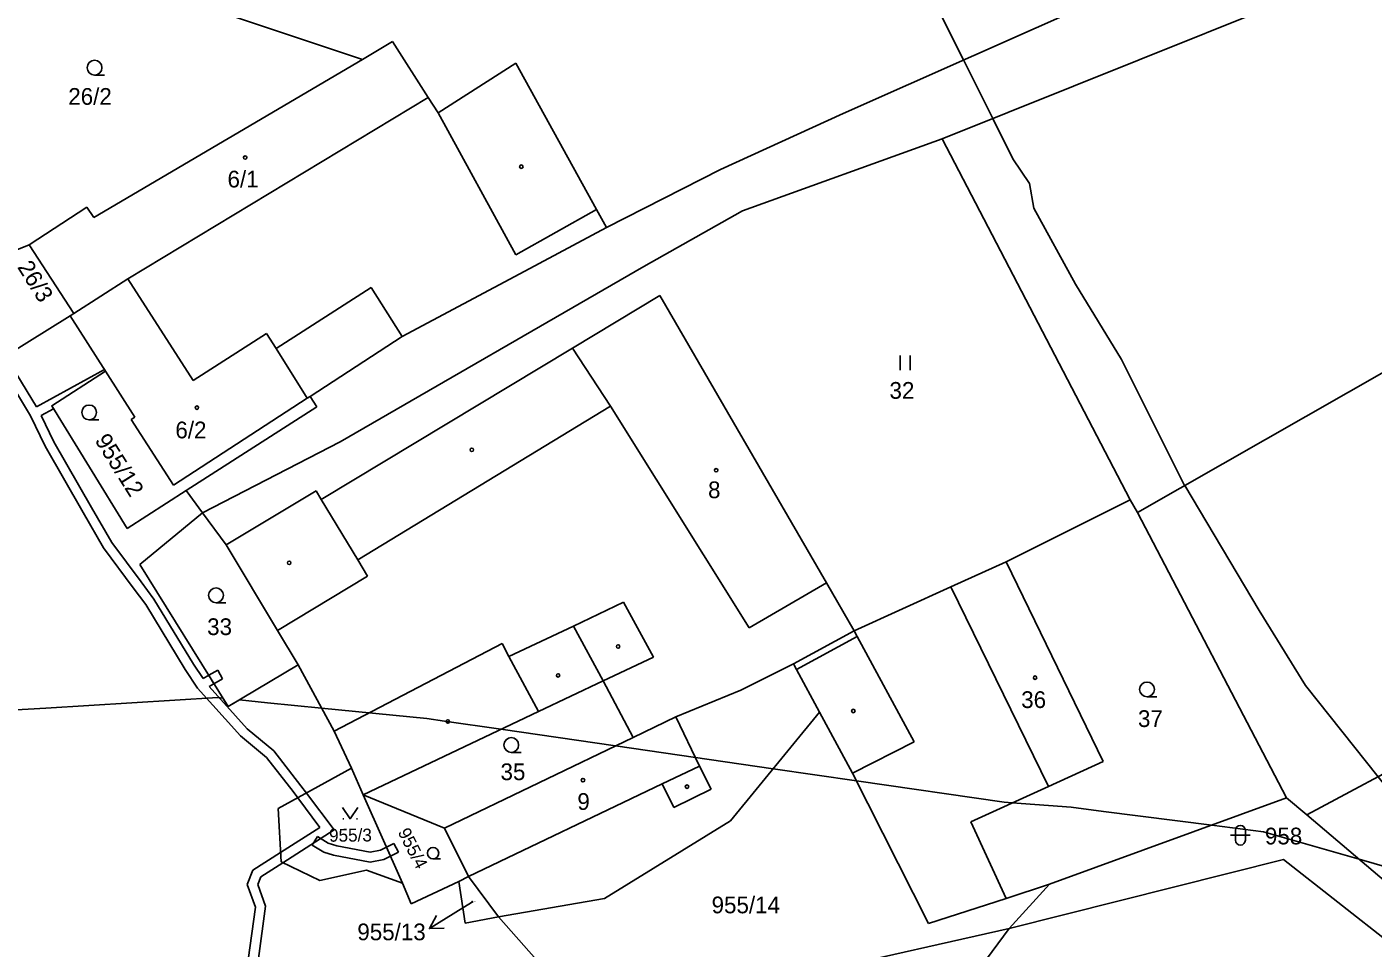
# Model space of a CAD drawing. Extents: x -749173 to -746119, y -1132678 to -1130338.
# Drawn here: x -747827.1 to -747690.2, y -1130989.1 to -1130895.5 of the extents above; entities that cross this region are included whole.
import ezdxf

# ---------------------------------------------------------------- set-up
doc = ezdxf.new("R2010")
doc.units = 0
for name, color, linetype in [('Vrstva 1', 7, 'Continuous'), ('Vrstva 16', 7, 'Continuous'), ('Vrstva 18', 7, 'Continuous'), ('Vrstva 19', 7, 'Continuous'), ('Vrstva 25', 7, 'Continuous'), ('Vrstva 3', 7, 'Continuous'), ('Vrstva 30', 7, 'Continuous'), ('Vrstva 37', 7, 'Continuous'), ('Vrstva 4', 7, 'Continuous'), ('Vrstva 52', 7, 'Continuous'), ('Vrstva 6', 7, 'Continuous')]:
    doc.layers.add(name, color=color, linetype=linetype)

msp = doc.modelspace()

# ---------------------------------------------------------------- linework, layer by layer
at = {"layer": 'Vrstva 1'}
for p, q in [((-747831.83, -1130919.6), (-747826.88, -1130917.6)), ((-747822.73, -1130924.82), (-747829.18, -1130928.84))]:
    msp.add_line(p, q, dxfattribs=at)
for points in [[(-747680.49, -1130885.34), (-747734.07, -1130906.85)], [(-747825.73, -1130887.83), (-747793.01, -1130898.76)], [(-747744.11, -1130904.25), (-747711.23, -1130889.62)], [(-747793.01, -1130898.76), (-747789.93, -1130896.95)], [(-747789.93, -1130896.95), (-747786.33, -1130902.63)], [(-747793.01, -1130898.76), (-747820.31, -1130914.83)], [(-747785.31, -1130904.19), (-747777.39, -1130899.14)], [(-747777.39, -1130899.14), (-747769.2, -1130914.03)], [(-747786.33, -1130902.63), (-747785.31, -1130904.19)], [(-747756.58, -1130909.94), (-747744.11, -1130904.25)], [(-747754.36, -1130914.15), (-747734.07, -1130906.85)], [(-747734.07, -1130906.85), (-747714.93, -1130943.52)], [(-747768.2, -1130915.84), (-747756.58, -1130909.94)], [(-747826.88, -1130917.6), (-747821.04, -1130913.77)], [(-747821.04, -1130913.77), (-747820.31, -1130914.83)], [(-747769.2, -1130914.03), (-747768.2, -1130915.84)], [(-747764.38, -1130919.82), (-747754.36, -1130914.15)], [(-747776.49, -1130920.27), (-747768.2, -1130915.84)], [(-747822.35, -1130924.58), (-747826.88, -1130917.6)], [(-747795.26, -1130937.61), (-747764.38, -1130919.82)], [(-747816.84, -1130921.05), (-747822.35, -1130924.58)], [(-747810.2, -1130931.39), (-747816.84, -1130921.05)], [(-747788.95, -1130926.93), (-747776.49, -1130920.27)], [(-747801.79, -1130928.13), (-747792.11, -1130921.93)], [(-747788.95, -1130926.93), (-747792.11, -1130921.93)], [(-747762.77, -1130922.74), (-747771.66, -1130928.1)], [(-747745.82, -1130951.95), (-747762.77, -1130922.74)], [(-747822.73, -1130924.82), (-747822.35, -1130924.58)], [(-747819.12, -1130930.45), (-747822.73, -1130924.82)], [(-747802.76, -1130926.61), (-747810.2, -1130931.39)], [(-747802.76, -1130926.61), (-747801.79, -1130928.13)], [(-747798.33, -1130933.02), (-747788.95, -1130926.93)], [(-747771.66, -1130928.1), (-747797.2, -1130943.47)], [(-747819.12, -1130930.45), (-747824.59, -1130933.96)], [(-747816.13, -1130935.12), (-747819.12, -1130930.45)], [(-747812.22, -1130942.04), (-747798.61, -1130933.2)], [(-747798.61, -1130933.2), (-747798.33, -1130933.02)], [(-747798.33, -1130933.02), (-747797.65, -1130934.06)], [(-747816.91, -1130946.43), (-747824.59, -1130933.96)], [(-747797.65, -1130934.06), (-747810.92, -1130942.58)], [(-747816.51, -1130935.36), (-747816.13, -1130935.12)], [(-747812.22, -1130942.04), (-747816.51, -1130935.36)], [(-747809.25, -1130944.84), (-747795.26, -1130937.61)], [(-747810.92, -1130942.58), (-747816.91, -1130946.43)], [(-747809.25, -1130944.84), (-747810.92, -1130942.58)], [(-747806.85, -1130948.1), (-747797.72, -1130942.61)], [(-747797.72, -1130942.61), (-747797.2, -1130943.47)], [(-747714.93, -1130943.52), (-747727.56, -1130949.81)], [(-747714.93, -1130943.52), (-747714.21, -1130944.8)], [(-747815.62, -1130950.1), (-747809.25, -1130944.84)], [(-747806.85, -1130948.1), (-747809.25, -1130944.84)], [(-747714.21, -1130944.8), (-747699.04, -1130973.8)], [(-747801.65, -1130956.79), (-747806.85, -1130948.1)], [(-747727.56, -1130949.81), (-747733.16, -1130952.36)], [(-747727.56, -1130949.81), (-747717.69, -1130970.09)], [(-747806.65, -1130964.52), (-747815.62, -1130950.1)], [(-747745.82, -1130951.95), (-747743.01, -1130956.84)], [(-747733.16, -1130952.36), (-747743.01, -1130956.84)], [(-747801.65, -1130956.79), (-747799.54, -1130960.27)], [(-747749.19, -1130960.19), (-747743.01, -1130956.84)], [(-747799.54, -1130960.27), (-747806.65, -1130964.52)], [(-747795.87, -1130967.04), (-747799.54, -1130960.27)], [(-747754.52, -1130962.87), (-747749.19, -1130960.19)], [(-747749.19, -1130960.19), (-747748.88, -1130960.76)], [(-747748.88, -1130960.76), (-747746.53, -1130965.11)], [(-747775.11, -1130965.02), (-747768.52, -1130961.91)], [(-747768.52, -1130961.91), (-747765.48, -1130967.66)], [(-747761.14, -1130965.57), (-747754.52, -1130962.87)], [(-747775.11, -1130965.02), (-747792.94, -1130973.48)], [(-747761.14, -1130965.57), (-747765.48, -1130967.66)], [(-747755.59, -1130976.12), (-747746.53, -1130965.11)], [(-747746.53, -1130965.11), (-747743.17, -1130971.3)], [(-747794.11, -1130970.77), (-747795.87, -1130967.04)], [(-747765.48, -1130967.66), (-747784.66, -1130976.88)], [(-747717.69, -1130970.09), (-747723.26, -1130972.63)], [(-747794.11, -1130970.77), (-747801.56, -1130974.89)], [(-747792.94, -1130973.48), (-747794.11, -1130970.77)], [(-747735.45, -1130986.58), (-747743.17, -1130971.3)], [(-747723.26, -1130972.63), (-747731.13, -1130976.23)], [(-747792.94, -1130973.48), (-747784.66, -1130976.88)], [(-747788.92, -1130982.46), (-747792.94, -1130973.48)], [(-747723.14, -1130982.58), (-747699.04, -1130973.8)], [(-747699.04, -1130973.8), (-747696.99, -1130975.53)], [(-747801.56, -1130974.89), (-747801.28, -1130980.31)], [(-747696.99, -1130975.53), (-747670.43, -1130998.05)], [(-747784.66, -1130976.88), (-747782.22, -1130981.78)], [(-747768.38, -1130984.02), (-747755.59, -1130976.12)], [(-747731.13, -1130976.23), (-747727.55, -1130984.01)], [(-747699.35, -1130980.06), (-747727.26, -1130987.09)], [(-747677.24, -1130997.39), (-747699.35, -1130980.06)], [(-747801.28, -1130980.31), (-747797.32, -1130982.19)], [(-747797.32, -1130982.19), (-747792.6, -1130981.16)], [(-747792.6, -1130981.16), (-747788.92, -1130982.46)], [(-747788.06, -1130984.58), (-747788.92, -1130982.46)], [(-747783.2, -1130982.29), (-747788.06, -1130984.58)], [(-747783.2, -1130982.29), (-747782.22, -1130981.78)], [(-747782.56, -1130986.54), (-747783.2, -1130982.29)], [(-747779.16, -1130985.88), (-747782.22, -1130981.78)], [(-747723.14, -1130982.58), (-747727.55, -1130984.01)], [(-747727.26, -1130987.09), (-747723.14, -1130982.58)], [(-747779.16, -1130985.88), (-747768.38, -1130984.02)], [(-747727.55, -1130984.01), (-747735.45, -1130986.58)], [(-747779.16, -1130985.88), (-747782.56, -1130986.54)], [(-747774.01, -1130991.73), (-747779.16, -1130985.88)], [(-747746.19, -1130991.34), (-747727.26, -1130987.09)], [(-747727.26, -1130987.09), (-747735.98, -1130998.89)]]:
    msp.add_lwpolyline(points, dxfattribs=at)
at = {"layer": 'Vrstva 16'}
msp.add_line((-747784.69, -1130987.05), (-747786.19, -1130987.09), dxfattribs=at)
for points in [[(-747782.79, -1130984.99), (-747786.19, -1130987.09), (-747785.48, -1130985.77)], [(-747781.73, -1130984.34), (-747782.79, -1130984.99)]]:
    msp.add_lwpolyline(points, dxfattribs=at)
at = {"layer": 'Vrstva 25'}
for p, q in [((-747820.24, -1130900.36), (-747819.24, -1130900.36)), ((-747738.32, -1130928.86), (-747738.32, -1130930.36)), ((-747737.32, -1130930.36), (-747737.32, -1130928.86)), ((-747820.79, -1130935.39), (-747819.79, -1130935.39)), ((-747807.89, -1130953.97), (-747806.89, -1130953.97)), ((-747713.23, -1130963.53), (-747712.23, -1130963.53)), ((-747777.87, -1130969.18), (-747776.87, -1130969.18)), ((-747794.98, -1130975.92), (-747794.9, -1130975.92)), ((-747793.6, -1130975.92), (-747793.52, -1130975.92)), ((-747704.23, -1130977.1), (-747704.23, -1130978.1)), ((-747703.23, -1130977.1), (-747703.23, -1130978.1)), ((-747704.73, -1130977.6), (-747702.73, -1130977.6)), ((-747785.82, -1130980), (-747785.05, -1130980))]:
    msp.add_line(p, q, dxfattribs=at)
msp.add_lwpolyline([(-747795.02, -1130974.77), (-747794.25, -1130975.92), (-747793.48, -1130974.77)], dxfattribs=at)
for centre, radius in [((-747820.24, -1130899.61), 0.75), ((-747804.92, -1130908.74), 0.175), ((-747776.85, -1130909.67), 0.175), ((-747820.79, -1130934.64), 0.75), ((-747809.83, -1130934.15), 0.175), ((-747781.88, -1130938.44), 0.175), ((-747757.04, -1130940.51), 0.175), ((-747800.45, -1130949.92), 0.175), ((-747807.89, -1130953.22), 0.75), ((-747767.01, -1130958.42), 0.175), ((-747773.11, -1130961.36), 0.175), ((-747724.61, -1130961.59), 0.175), ((-747713.23, -1130962.78), 0.75), ((-747743.09, -1130964.97), 0.175), ((-747784.33, -1130966.04), 0.175), ((-747777.87, -1130968.43), 0.75), ((-747770.58, -1130972), 0.175), ((-747760, -1130972.66), 0.175), ((-747785.82, -1130979.42), 0.577)]:
    msp.add_circle(centre, radius, dxfattribs=at)
for centre, start, end in [((-747703.73, -1130977.1), 0, 180), ((-747703.73, -1130978.1), 180, 0)]:
    msp.add_arc(centre, 0.5, start, end, dxfattribs=at)
at = {"layer": 'Vrstva 3'}
for points in [[(-747793.01, -1130898.76), (-747789.93, -1130896.95)], [(-747789.93, -1130896.95), (-747786.33, -1130902.63)], [(-747793.01, -1130898.76), (-747820.31, -1130914.83)], [(-747786.33, -1130902.63), (-747816.84, -1130921.05)], [(-747826.88, -1130917.6), (-747821.04, -1130913.77)], [(-747821.04, -1130913.77), (-747820.31, -1130914.83)], [(-747822.35, -1130924.58), (-747826.88, -1130917.6)], [(-747816.84, -1130921.05), (-747822.35, -1130924.58)], [(-747816.84, -1130921.05), (-747822.35, -1130924.58)], [(-747810.2, -1130931.39), (-747816.84, -1130921.05)], [(-747762.77, -1130922.74), (-747771.66, -1130928.1)], [(-747745.82, -1130951.95), (-747762.77, -1130922.74)], [(-747822.73, -1130924.82), (-747822.35, -1130924.58)], [(-747819.12, -1130930.45), (-747822.73, -1130924.82)], [(-747802.76, -1130926.61), (-747810.2, -1130931.39)], [(-747802.76, -1130926.61), (-747801.79, -1130928.13)], [(-747801.79, -1130928.13), (-747798.61, -1130933.2)], [(-747767.79, -1130934.01), (-747771.66, -1130928.1)], [(-747816.13, -1130935.12), (-747819.12, -1130930.45)], [(-747812.22, -1130942.04), (-747798.61, -1130933.2)], [(-747753.68, -1130956.54), (-747767.79, -1130934.01)], [(-747816.51, -1130935.36), (-747816.13, -1130935.12)], [(-747812.22, -1130942.04), (-747816.51, -1130935.36)], [(-747727.56, -1130949.81), (-747733.16, -1130952.36)], [(-747727.56, -1130949.81), (-747717.69, -1130970.09)], [(-747753.68, -1130956.54), (-747745.82, -1130951.95)], [(-747733.16, -1130952.36), (-747723.26, -1130972.63)], [(-747761.14, -1130965.57), (-747765.48, -1130967.66)], [(-747761.14, -1130965.57), (-747758.74, -1130970.57)], [(-747765.48, -1130967.66), (-747784.66, -1130976.88)], [(-747717.69, -1130970.09), (-747723.26, -1130972.63)], [(-747758.74, -1130970.57), (-747762.53, -1130972.38)], [(-747762.53, -1130972.38), (-747782.22, -1130981.78)], [(-747784.66, -1130976.88), (-747782.22, -1130981.78)]]:
    msp.add_lwpolyline(points, dxfattribs=at)
at = {"layer": 'Vrstva 30'}
for p, q in [((-747798.1, -1130978.6), (-747797.58, -1130977.74)), ((-747796.92, -1130979.32), (-747798.1, -1130978.6)), ((-747797.58, -1130977.74), (-747796.5, -1130978.4)), ((-747796.5, -1130978.4), (-747795.62, -1130978.68)), ((-747795.62, -1130978.68), (-747792.21, -1130979.32)), ((-747790.55, -1130978.81), (-747789.81, -1130978.43)), ((-747789.81, -1130978.43), (-747789.35, -1130979.32)), ((-747795.94, -1130979.64), (-747796.92, -1130979.32)), ((-747792.21, -1130980.34), (-747795.94, -1130979.64)), ((-747792.21, -1130979.32), (-747791.16, -1130979.12)), ((-747790.81, -1130980.07), (-747792.21, -1130980.34)), ((-747791.16, -1130979.12), (-747790.55, -1130978.81)), ((-747790.14, -1130979.73), (-747790.81, -1130980.07)), ((-747789.35, -1130979.32), (-747790.14, -1130979.73))]:
    msp.add_line(p, q, dxfattribs=at)
for points in [[(-747826.76, -1130934.98), (-747830.55, -1130928.71)], [(-747829.65, -1130928.27), (-747826.14, -1130934.07)], [(-747826.14, -1130934.07), (-747819.23, -1130930.28)], [(-747819.23, -1130930.28), (-747819.12, -1130930.45), (-747824.59, -1130933.96), (-747824.41, -1130934.26)], [(-747824.41, -1130934.26), (-747825.66, -1130934.95)], [(-747825.25, -1130938.07), (-747826.76, -1130934.98)], [(-747825.66, -1130934.95), (-747824.37, -1130937.61)], [(-747824.37, -1130937.61), (-747820.54, -1130944.3)], [(-747821.4, -1130944.8), (-747825.25, -1130938.07)], [(-747820.54, -1130944.3), (-747818.49, -1130947.87)], [(-747819.33, -1130948.41), (-747821.4, -1130944.8)], [(-747816.31, -1130952.46), (-747819.33, -1130948.41)], [(-747818.49, -1130947.87), (-747815.51, -1130951.86)], [(-747815.04, -1130954.16), (-747816.31, -1130952.46)], [(-747815.51, -1130951.86), (-747814.2, -1130953.6)], [(-747814.2, -1130953.6), (-747810.17, -1130960.22)], [(-747811.01, -1130960.76), (-747815.04, -1130954.16)], [(-747809.76, -1130962.66), (-747811.01, -1130960.76)], [(-747810.17, -1130960.22), (-747809.2, -1130961.68)], [(-747808.62, -1130961.35), (-747807.72, -1130960.82)], [(-747807.72, -1130960.82), (-747807.22, -1130961.69)], [(-747809.2, -1130961.68), (-747808.62, -1130961.35)], [(-747808.62, -1130961.35), (-747808.1, -1130962.2)], [(-747808.1, -1130962.2), (-747808.62, -1130961.35)], [(-747808.1, -1130962.2), (-747808.57, -1130962.47)], [(-747807.22, -1130961.69), (-747808.1, -1130962.2)], [(-747805.41, -1130967.49), (-747809.76, -1130962.66)], [(-747808.57, -1130962.47), (-747804.71, -1130966.77)], [(-747802.74, -1130969.71), (-747805.41, -1130967.49)], [(-747804.71, -1130966.77), (-747802.02, -1130969.01)], [(-747802.02, -1130969.01), (-747799.25, -1130972.57)], [(-747800.05, -1130973.17), (-747802.74, -1130969.71)], [(-747799.58, -1130973.79), (-747800.05, -1130973.17)], [(-747799.25, -1130972.57), (-747798.7, -1130973.31)], [(-747797.32, -1130976.8), (-747799.58, -1130973.79)], [(-747798.7, -1130973.31), (-747795.87, -1130977.06)], [(-747801.33, -1130979.36), (-747797.32, -1130976.8)], [(-747795.87, -1130977.06), (-747801.09, -1130980.4)], [(-747804.14, -1130981.16), (-747801.33, -1130979.36)], [(-747790.14, -1130979.73), (-747790.55, -1130978.81)], [(-747790.55, -1130978.81), (-747790.14, -1130979.73)], [(-747804.73, -1130982.6), (-747804.14, -1130981.16)], [(-747801.09, -1130980.4), (-747803.34, -1130981.84)], [(-747803.87, -1130984.91), (-747804.73, -1130982.6)], [(-747803.34, -1130981.84), (-747803.65, -1130982.61)], [(-747803.65, -1130982.61), (-747802.85, -1130984.79)], [(-747804.61, -1130990.26), (-747803.87, -1130984.91)], [(-747802.85, -1130984.79), (-747803.58, -1130990.11)]]:
    msp.add_lwpolyline(points, dxfattribs=at)
at = {"layer": 'Vrstva 37'}
for centre in [(-747804.92, -1130908.74), (-747809.83, -1130934.15), (-747757.04, -1130940.51), (-747724.61, -1130961.59), (-747770.58, -1130972)]:
    msp.add_circle(centre, 0.175, dxfattribs=at)
at = {"layer": 'Vrstva 4'}
for points in [[(-747786.33, -1130902.63), (-747816.84, -1130921.05)], [(-747785.31, -1130904.19), (-747777.39, -1130918.63)], [(-747769.2, -1130914.03), (-747777.39, -1130918.63)], [(-747801.79, -1130928.13), (-747798.61, -1130933.2)], [(-747767.79, -1130934.01), (-747771.66, -1130928.1)], [(-747793.47, -1130949.63), (-747767.79, -1130934.01)], [(-747753.68, -1130956.54), (-747767.79, -1130934.01)], [(-747797.2, -1130943.47), (-747793.47, -1130949.63)], [(-747793.47, -1130949.63), (-747792.49, -1130951.26)], [(-747801.65, -1130956.79), (-747792.49, -1130951.26)], [(-747753.68, -1130956.54), (-747745.82, -1130951.95)], [(-747733.16, -1130952.36), (-747723.26, -1130972.63)], [(-747766.45, -1130953.93), (-747771.54, -1130956.35)], [(-747763.42, -1130959.49), (-747766.45, -1130953.93)], [(-747771.54, -1130956.35), (-747778.1, -1130959.43)], [(-747771.54, -1130956.35), (-747768.52, -1130961.91)], [(-747778.81, -1130958.12), (-747795.87, -1130967.04)], [(-747778.81, -1130958.12), (-747778.1, -1130959.43)], [(-747748.88, -1130960.76), (-747742.69, -1130957.41)], [(-747742.69, -1130957.41), (-747743.01, -1130956.84)], [(-747736.92, -1130968.11), (-747742.69, -1130957.41)], [(-747778.1, -1130959.43), (-747775.11, -1130965.02)], [(-747768.52, -1130961.91), (-747763.42, -1130959.49)], [(-747761.14, -1130965.57), (-747758.74, -1130970.57)], [(-747743.17, -1130971.3), (-747736.92, -1130968.11)], [(-747758.74, -1130970.57), (-747762.53, -1130972.38)], [(-747758.74, -1130970.57), (-747757.54, -1130972.91)], [(-747762.53, -1130972.38), (-747782.22, -1130981.78)], [(-747761.33, -1130974.79), (-747762.53, -1130972.38)], [(-747757.54, -1130972.91), (-747761.33, -1130974.79)]]:
    msp.add_lwpolyline(points, dxfattribs=at)
at = {"layer": 'Vrstva 52'}
for points in [[(-747756.37, -1130835.62), (-747756.6, -1130837.87), (-747756.78, -1130839.59), (-747757.5, -1130846.75), (-747757.45, -1130846.89), (-747756.2, -1130850.2), (-747752.37, -1130860.37), (-747749, -1130865.5), (-747743.06, -1130878.25), (-747734.56, -1130893.5), (-747731.9, -1130898.82), (-747728.92, -1130904.78), (-747726.87, -1130908.87), (-747725.19, -1130911.37), (-747724.75, -1130913.87), (-747720.5, -1130921.62), (-747715.81, -1130929.25), (-747709.44, -1130942), (-747709.4, -1130942.06), (-747701.81, -1130954.75), (-747697.12, -1130962.37), (-747689.74, -1130971.65), (-747680.5, -1130983.25)], [(-747807.18, -1130963.67), (-747807.69, -1130963.62), (-747825.18, -1130964.67), (-747830.62, -1130965), (-747855.31, -1130969.25), (-747866.73, -1130969.86), (-747869.37, -1130970), (-747877.95, -1130971.96), (-747890.19, -1130974.75), (-747897.57, -1130975.89), (-747898.25, -1130976), (-747904.91, -1130977.89), (-747921.73, -1130982.67), (-747937.37, -1130987.12), (-747943.37, -1130989.25), (-747945.09, -1130990.33), (-747946.75, -1130991.37), (-747956.65, -1130995.11), (-747964.08, -1130997.92), (-747965.94, -1130998.62), (-747967.99, -1130999.4), (-747987.69, -1131006.84)], [(-747680.5, -1130983.25), (-747691.67, -1130980.04), (-747701.37, -1130977.25), (-747706.65, -1130976.57), (-747717.66, -1130975.17), (-747720.94, -1130974.75), (-747726.93, -1130974.31), (-747727.75, -1130974.25), (-747742.78, -1130972.07), (-747751.25, -1130970.84), (-747767.28, -1130968.52), (-747778.94, -1130966.83), (-747784.65, -1130966.01), (-747786.44, -1130965.75), (-747797.15, -1130964.68), (-747802.66, -1130964.13), (-747805.51, -1130963.84), (-747806.65, -1130964.52), (-747807.18, -1130963.67)]]:
    msp.add_lwpolyline(points, dxfattribs=at)
at = {"layer": 'Vrstva 6'}
for points in [[(-747658.27, -1130912.95), (-747714.21, -1130944.8)], [(-747672.66, -1130962.51), (-747696.99, -1130975.53)]]:
    msp.add_lwpolyline(points, dxfattribs=at)

# ---------------------------------------------------------------- texts
at = {"layer": 'Vrstva 16'}
msp.add_text('955/13', height=1.7, dxfattribs=at).set_placement((-747793.52, -1130988.27))
at = {"layer": 'Vrstva 18'}
for s, height, p in [('26/2', 1.7, (-747822.91, -1130903.38)), ('32', 1.7, (-747739.41, -1130933.25)), ('33', 1.7, (-747808.79, -1130957.26)), ('37', 1.7, (-747714.15, -1130966.6)), ('35', 1.7, (-747778.96, -1130972)), ('958', 1.7, (-747701.24, -1130978.53)), ('955/14', 1.7, (-747757.5, -1130985.53)), ('955/13', 0.1, (-747781.94, -1130984.34))]:
    msp.add_text(s, height=height, dxfattribs=at).set_placement(p)
for s, height, rotation, p in [('26/3', 1.7, 302.0911, (-747828.14, -1130919.87)), ('955/12', 1.7, 302.0472, (-747820.27, -1130937.47)), ('955/3', 1.3, 0.4743, (-747796.39, -1130978.26)), ('955/4', 1.3, 296.7839, (-747789.44, -1130977.27))]:
    msp.add_text(s, height=height, rotation=rotation, dxfattribs=at).set_placement(p)
at = {"layer": 'Vrstva 19'}
for s, p in [('6/1', (-747806.72, -1130911.78)), ('6/2', (-747812.02, -1130937.27)), ('8', (-747757.86, -1130943.35)), ('36', (-747726.02, -1130964.67)), ('9', (-747771.15, -1130975.02))]:
    msp.add_text(s, height=1.7, dxfattribs=at).set_placement(p)

doc.saveas('drawing.dxf')
